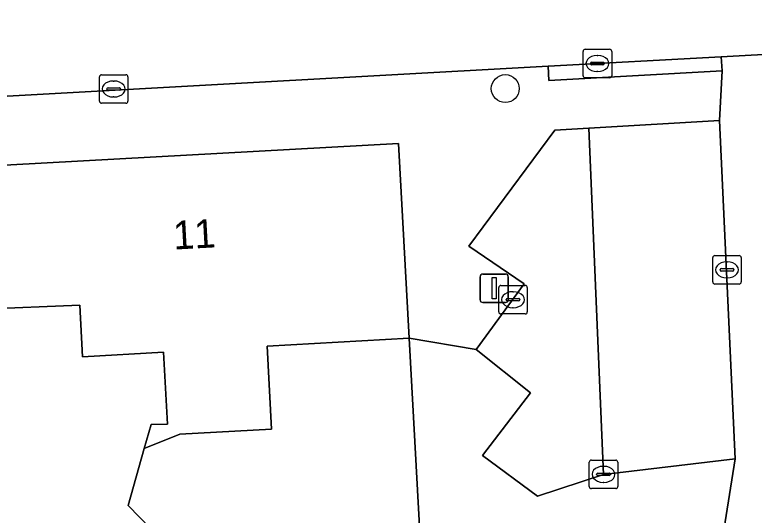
# Model space of a CAD drawing. Extents: x 160856 to 161310, y 384024 to 384878.
# Drawn here: x 161083.27 to 161109.19, y 384700.97 to 384718.5 of the extents above; entities that cross this region are included whole.
import ezdxf

# ---------------------------------------------------------------- set-up
doc = ezdxf.new("R2010")
doc.units = 0
for name, color, linetype in [('IMGEO_Boom', 7, 'Continuous'), ('IMGEO_Erf', 7, 'Continuous'), ('IMGEO_Kolk', 7, 'Continuous'), ('IMGEO_Lichtmast', 7, 'Continuous'), ('IMGEO_Pand', 7, 'Continuous'), ('IMGEO_Pand_nummerreeks', 7, 'Continuous'), ('IMGEO_Parkeervlak_open', 7, 'Continuous'), ('IMGEO_Rijbaan_lokaal_open', 7, 'Continuous'), ('IMGEO_Voetpad_open', 7, 'Continuous')]:
    doc.layers.add(name, color=color, linetype=linetype)

msp = doc.modelspace()

# ---------------------------------------------------------------- linework, layer by layer
at = {"layer": 'IMGEO_Boom'}
msp.add_circle((161100.463, 384715.916), 0.489, dxfattribs=at)
at = {"layer": 'IMGEO_Erf'}
msp.add_lwpolyline([(161079.327, 384688.593), (161085.753, 384694.857), (161088.098, 384697.142), (161087.197, 384698.066), (161088.843, 384699.67), (161087.24, 384701.315), (161087.809, 384703.308), (161088.049, 384704.147), (161088.617, 384704.156), (161088.476, 384706.684), (161085.645, 384706.524), (161085.546, 384708.334), (161082.119, 384708.186)], dxfattribs=at)
at = {"layer": 'IMGEO_Kolk'}
for p, q in [((161103.267, 384717.295), (161104.119, 384717.295)), ((161103.192, 384716.369), (161103.192, 384717.221)), ((161103.68, 384717.075), (161103.705, 384717.075)), ((161104.193, 384717.221), (161104.193, 384716.369)), ((161103.451, 384716.789), (161103.451, 384716.801)), ((161103.889, 384716.752), (161103.491, 384716.752)), ((161103.494, 384716.838), (161103.892, 384716.838)), ((161103.935, 384716.801), (161103.935, 384716.789)), ((161103.703, 384716.515), (161103.678, 384716.515)), ((161086.235, 384715.477), (161086.235, 384716.329)), ((161086.31, 384716.403), (161087.162, 384716.403)), ((161087.236, 384716.329), (161087.236, 384715.477)), ((161104.119, 384716.295), (161103.267, 384716.295)), ((161086.723, 384716.183), (161086.748, 384716.183)), ((161086.494, 384715.897), (161086.494, 384715.909)), ((161086.932, 384715.86), (161086.534, 384715.86)), ((161086.537, 384715.946), (161086.935, 384715.946)), ((161086.978, 384715.909), (161086.978, 384715.897)), ((161086.746, 384715.623), (161086.721, 384715.623)), ((161087.162, 384715.403), (161086.31, 384715.403)), ((161107.81, 384710.068), (161108.662, 384710.068)), ((161107.735, 384709.142), (161107.735, 384709.994)), ((161108.223, 384709.848), (161108.248, 384709.848)), ((161108.736, 384709.994), (161108.736, 384709.142)), ((161107.994, 384709.562), (161107.994, 384709.574)), ((161108.432, 384709.525), (161108.034, 384709.525)), ((161108.037, 384709.611), (161108.435, 384709.611)), ((161108.478, 384709.574), (161108.478, 384709.562)), ((161108.246, 384709.288), (161108.221, 384709.288)), ((161100.309, 384709.021), (161101.161, 384709.021)), ((161108.662, 384709.068), (161107.81, 384709.068)), ((161100.234, 384708.095), (161100.234, 384708.947)), ((161100.722, 384708.801), (161100.747, 384708.801)), ((161101.235, 384708.947), (161101.235, 384708.095)), ((161100.493, 384708.515), (161100.493, 384708.527)), ((161100.931, 384708.478), (161100.533, 384708.478)), ((161100.536, 384708.564), (161100.934, 384708.564)), ((161100.977, 384708.527), (161100.977, 384708.515)), ((161100.745, 384708.241), (161100.72, 384708.241)), ((161101.161, 384708.021), (161100.309, 384708.021)), ((161103.407, 384701.976), (161103.407, 384702.828)), ((161103.482, 384702.902), (161104.334, 384702.902)), ((161104.408, 384702.828), (161104.408, 384701.976)), ((161103.895, 384702.682), (161103.92, 384702.682)), ((161103.666, 384702.396), (161103.666, 384702.408)), ((161104.104, 384702.359), (161103.706, 384702.359)), ((161103.709, 384702.445), (161104.107, 384702.445)), ((161104.15, 384702.408), (161104.15, 384702.396)), ((161103.918, 384702.122), (161103.893, 384702.122)), ((161104.334, 384701.902), (161103.482, 384701.902))]:
    msp.add_line(p, q, dxfattribs=at)
for points in [[(161103.267, 384717.295), (161104.119, 384717.295)], [(161103.192, 384716.369), (161103.192, 384717.221)], [(161104.193, 384717.221), (161104.193, 384716.369)], [(161086.235, 384715.477), (161086.235, 384716.329)], [(161086.31, 384716.403), (161087.162, 384716.403)], [(161087.236, 384716.329), (161087.236, 384715.477)], [(161104.119, 384716.295), (161103.267, 384716.295)], [(161087.162, 384715.403), (161086.31, 384715.403)], [(161107.81, 384710.068), (161108.662, 384710.068)], [(161107.735, 384709.142), (161107.735, 384709.994)], [(161108.736, 384709.994), (161108.736, 384709.142)], [(161100.309, 384709.021), (161101.161, 384709.021)], [(161108.662, 384709.068), (161107.81, 384709.068)], [(161100.234, 384708.095), (161100.234, 384708.947)], [(161101.235, 384708.947), (161101.235, 384708.095)], [(161101.161, 384708.021), (161100.309, 384708.021)], [(161103.407, 384701.976), (161103.407, 384702.828)], [(161103.482, 384702.902), (161104.334, 384702.902)], [(161104.408, 384702.828), (161104.408, 384701.976)], [(161104.334, 384701.902), (161103.482, 384701.902)]]:
    msp.add_lwpolyline(points, dxfattribs=at)
for centre, radius, start, end in [((161103.269, 384717.219), 0.0765, 91.552, 178.448), ((161103.269, 384717.219), 0.0765, 91.552, 178.448), ((161104.117, 384717.219), 0.0765, 1.552, 88.448), ((161104.117, 384717.219), 0.0765, 1.552, 88.448), ((161103.491, 384716.798), 0.0403, 85.8775, 175.7526), ((161103.488, 384716.788), 0.0366, 178.938, 274.7102), ((161103.892, 384716.795), 0.043, 264.8664, 352.4533), ((161103.896, 384716.8), 0.0386, 1.7309, 96.639), ((161086.312, 384716.327), 0.0765, 91.552, 178.448), ((161086.312, 384716.327), 0.0765, 91.552, 178.448), ((161087.16, 384716.327), 0.0765, 1.552, 88.448), ((161087.16, 384716.327), 0.0765, 1.552, 88.448), ((161103.269, 384716.371), 0.0765, 181.552, 268.448), ((161103.269, 384716.371), 0.0765, 181.552, 268.448), ((161104.117, 384716.371), 0.0765, 271.552, 358.448), ((161104.117, 384716.371), 0.0765, 271.552, 358.448), ((161086.534, 384715.906), 0.0403, 85.8775, 175.7526), ((161086.531, 384715.896), 0.0366, 178.938, 274.7102), ((161086.935, 384715.903), 0.043, 264.8664, 352.4533), ((161086.939, 384715.908), 0.0386, 1.7309, 96.639), ((161086.312, 384715.479), 0.0765, 181.552, 268.448), ((161086.312, 384715.479), 0.0765, 181.552, 268.448), ((161087.16, 384715.479), 0.0765, 271.552, 358.448), ((161087.16, 384715.479), 0.0765, 271.552, 358.448), ((161107.812, 384709.992), 0.0765, 91.552, 178.448), ((161107.812, 384709.992), 0.0765, 91.552, 178.448), ((161108.66, 384709.992), 0.0765, 1.552, 88.448), ((161108.66, 384709.992), 0.0765, 1.552, 88.448), ((161108.034, 384709.571), 0.0403, 85.8775, 175.7526), ((161108.031, 384709.561), 0.0366, 178.938, 274.7102), ((161108.435, 384709.568), 0.043, 264.8664, 352.4533), ((161108.439, 384709.573), 0.0386, 1.7309, 96.639), ((161100.311, 384708.945), 0.0765, 91.552, 178.448), ((161100.311, 384708.945), 0.0765, 91.552, 178.448), ((161101.159, 384708.945), 0.0765, 1.552, 88.448), ((161101.159, 384708.945), 0.0765, 1.552, 88.448), ((161107.812, 384709.144), 0.0765, 181.552, 268.448), ((161107.812, 384709.144), 0.0765, 181.552, 268.448), ((161108.66, 384709.144), 0.0765, 271.552, 358.448), ((161108.66, 384709.144), 0.0765, 271.552, 358.448), ((161100.533, 384708.524), 0.0403, 85.8775, 175.7526), ((161100.53, 384708.514), 0.0366, 178.938, 274.7102), ((161100.934, 384708.521), 0.043, 264.8664, 352.4533), ((161100.938, 384708.526), 0.0386, 1.7309, 96.639), ((161100.311, 384708.097), 0.0765, 181.552, 268.448), ((161100.311, 384708.097), 0.0765, 181.552, 268.448), ((161101.159, 384708.097), 0.0765, 271.552, 358.448), ((161101.159, 384708.097), 0.0765, 271.552, 358.448), ((161103.484, 384702.826), 0.0765, 91.552, 178.448), ((161103.484, 384702.826), 0.0765, 91.552, 178.448), ((161104.332, 384702.826), 0.0765, 1.552, 88.448), ((161104.332, 384702.826), 0.0765, 1.552, 88.448), ((161103.706, 384702.405), 0.0403, 85.8775, 175.7526), ((161103.703, 384702.395), 0.0366, 178.938, 274.7102), ((161104.107, 384702.402), 0.043, 264.8664, 352.4533), ((161104.111, 384702.407), 0.0386, 1.7309, 96.639), ((161103.484, 384701.978), 0.0765, 181.552, 268.448), ((161103.484, 384701.978), 0.0765, 181.552, 268.448), ((161104.332, 384701.978), 0.0765, 271.552, 358.448), ((161104.332, 384701.978), 0.0765, 271.552, 358.448)]:
    msp.add_arc(centre, radius, start, end, dxfattribs=at)
for centre, major_axis, ratio, start_param, end_param in [((161103.679, 384716.795), (-0.387, 0.002), 0.722429, 4.712389, 7.853982), ((161103.704, 384716.795), (-0.39, 0.002), 0.717154, 1.570796, 4.712389), ((161086.722, 384715.903), (-0.387, 0.002), 0.722429, 4.712389, 7.853982), ((161086.747, 384715.903), (-0.39, 0.002), 0.717154, 1.570796, 4.712389), ((161108.222, 384709.568), (-0.387, 0.002), 0.722429, 4.712389, 7.853982), ((161108.247, 384709.568), (-0.39, 0.002), 0.717154, 1.570796, 4.712389), ((161100.721, 384708.521), (-0.387, 0.002), 0.722429, 4.712389, 7.853982), ((161100.746, 384708.521), (-0.39, 0.002), 0.717154, 1.570796, 4.712389), ((161103.894, 384702.402), (-0.387, 0.002), 0.722429, 4.712389, 7.853982), ((161103.919, 384702.402), (-0.39, 0.002), 0.717154, 1.570796, 4.712389)]:
    msp.add_ellipse(centre, major_axis=major_axis, ratio=ratio, start_param=start_param, end_param=end_param, dxfattribs=at)
at = {"layer": 'IMGEO_Lichtmast'}
for p, q in [((161099.579, 384708.521), (161099.579, 384709.321)), ((161099.579, 384709.321), (161099.579, 384708.521)), ((161099.679, 384709.421), (161100.469, 384709.421)), ((161100.469, 384709.421), (161099.679, 384709.421)), ((161100.569, 384709.321), (161100.569, 384708.521)), ((161100.569, 384708.521), (161100.569, 384709.321)), ((161100.469, 384708.421), (161099.679, 384708.421)), ((161099.679, 384708.421), (161100.469, 384708.421))]:
    msp.add_line(p, q, dxfattribs=at)
msp.add_lwpolyline([(161099.999, 384709.296), (161100.149, 384709.296), (161100.149, 384708.546), (161099.999, 384708.546), (161099.999, 384709.296)], dxfattribs=at)
for centre, start, end in [((161099.679, 384709.321), 90, 180), ((161099.679, 384709.321), 90, 180), ((161100.469, 384709.321), 0, 90), ((161100.469, 384709.321), 360, 90), ((161099.679, 384708.521), 180, 270), ((161099.679, 384708.521), 180, 270), ((161100.469, 384708.521), 270, 0), ((161100.469, 384708.521), 270, 0)]:
    msp.add_arc(centre, 0.1, start, end, dxfattribs=at)
at = {"layer": 'IMGEO_Pand'}
for points in [[(161097.096, 384707.169), (161096.723, 384713.991), (161081.846, 384713.178), (161082.119, 384708.186), (161085.546, 384708.334), (161085.645, 384706.524), (161088.476, 384706.684), (161088.617, 384704.156), (161088.049, 384704.147), (161087.809, 384703.308), (161089.056, 384703.807), (161092.27, 384703.984), (161092.111, 384706.895)], [(161097.096, 384707.169), (161092.111, 384706.895), (161092.27, 384703.984), (161089.056, 384703.807), (161087.809, 384703.308), (161087.24, 384701.315), (161088.843, 384699.67), (161087.197, 384698.066), (161088.098, 384697.142), (161085.753, 384694.857), (161089.608, 384691.356), (161097.538, 384699.085)]]:
    msp.add_lwpolyline(points, close=True, dxfattribs=at)
at = {"layer": 'IMGEO_Parkeervlak_open'}
msp.add_lwpolyline([(161103.389, 384714.53), (161102.199, 384714.46), (161099.19, 384710.395), (161101.13, 384709.076), (161099.448, 384706.782), (161101.342, 384705.262), (161099.667, 384703.058), (161101.594, 384701.635), (161103.904, 384702.4)], close=True, dxfattribs=at)
at = {"layer": 'IMGEO_Rijbaan_lokaal_open'}
for points in [[(161071.831, 384718.54), (161072.03, 384715.044), (161101.964, 384716.699), (161108.035, 384717.035), (161121.139, 384717.759), (161120.943, 384721.23), (161119.828, 384721.163), (161119.802, 384721.162)], [(161107.975, 384714.798), (161103.389, 384714.53), (161103.904, 384702.4), (161108.517, 384702.943)]]:
    msp.add_lwpolyline(points, close=True, dxfattribs=at)
at = {"layer": 'IMGEO_Voetpad_open'}
for points in [[(161126.904, 384704.217), (161127.187, 384707.75), (161128.062, 384717.217), (161127.57, 384717.257), (161127.641, 384718.106), (161121.139, 384717.759), (161108.035, 384717.035), (161108.062, 384716.536), (161107.975, 384714.798), (161108.517, 384702.943), (161108.011, 384699.714), (161109.961, 384700.078)], [(161104.804, 384700.047), (161106.233, 384699.652), (161107.018, 384699.583), (161108.011, 384699.714), (161108.517, 384702.943), (161103.904, 384702.4), (161101.594, 384701.635), (161099.667, 384703.058), (161101.342, 384705.262), (161099.448, 384706.782), (161097.096, 384707.169), (161097.538, 384699.085), (161089.608, 384691.356), (161082.942, 384684.859)]]:
    msp.add_lwpolyline(points, dxfattribs=at)
for points in [[(161108.035, 384717.035), (161101.964, 384716.699), (161101.991, 384716.2), (161108.062, 384716.536)], [(161102.199, 384714.46), (161103.389, 384714.53), (161107.975, 384714.798), (161108.062, 384716.536), (161101.991, 384716.2), (161101.964, 384716.699), (161072.03, 384715.044), (161057.268, 384714.228), (161017.08, 384712.007), (161019.614, 384709.69), (161049.56, 384711.368), (161050.754, 384711.435), (161062.499, 384712.093), (161068.593, 384712.435), (161080.748, 384713.117), (161081.846, 384713.178), (161096.723, 384713.991), (161097.096, 384707.169), (161099.448, 384706.782), (161101.13, 384709.076), (161099.19, 384710.395)]]:
    msp.add_lwpolyline(points, close=True, dxfattribs=at)

# ---------------------------------------------------------------- texts
at = {"layer": 'IMGEO_Pand_nummerreeks'}
msp.add_text('11', height=1, rotation=3.128, dxfattribs=at).set_placement((161088.843, 384710.276))

doc.saveas('drawing.dxf')
